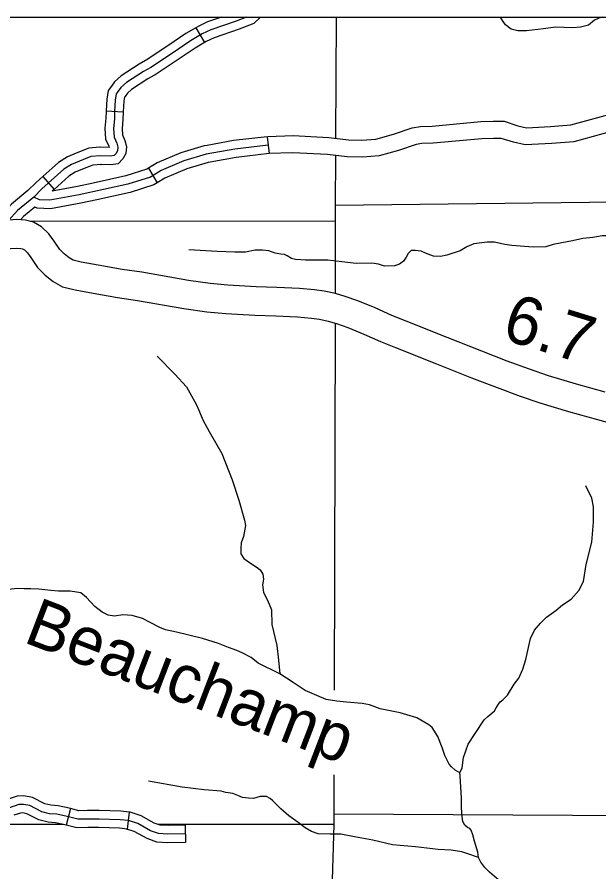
# Model space of a CAD drawing. Extents: x 22866 to 28196, y 1324810 to 1328105.
# Drawn here: x 25280.6 to 25403.3, y 1326401.4 to 1326581.6 of the extents above; entities that cross this region are included whole.
import ezdxf

# ---------------------------------------------------------------- set-up
doc = ezdxf.new("R2010")
doc.units = 0
for name, color, linetype in [('Level 10', 7, 'Continuous'), ('Level 31', 7, 'Continuous'), ('Level 32', 7, 'Continuous'), ('Level 35', 7, 'Continuous'), ('Level 4', 7, 'Continuous'), ('Level 45', 7, 'Continuous'), ('Level 46', 7, 'Continuous'), ('Level 48', 7, 'Continuous'), ('Level 5', 7, 'Continuous'), ('R_No Plot', 7, 'Continuous')]:
    doc.layers.add(name, color=color, linetype=linetype)

msp = doc.modelspace()

# ---------------------------------------------------------------- linework, layer by layer
at = {"layer": 'Level 10'}
for points in [[(25306.99, 1326527.83), (25302.79, 1326528.42), (25297.73, 1326529.32), (25294.15, 1326529.97), (25292.49, 1326530.36), (25291.63, 1326530.87), (25290.58, 1326531.68), (25289.65, 1326532.64), (25288.48, 1326534.39), (25287.37, 1326535.93), (25285.81, 1326537.38), (25284.08, 1326538.4), (25282.44, 1326538.8), (25280.58, 1326538.96), (25278.14, 1326538.75), (25276.47, 1326538.23), (25274.59, 1326537.5), (25272.48, 1326536.58), (25270.72, 1326535.55), (25268.77, 1326534.16), (25266.81, 1326532.28), (25263.07, 1326528.46)], [(25267.33, 1326524.24), (25271.03, 1326528.02), (25272.61, 1326529.53), (25273.97, 1326530.5), (25275.2, 1326531.21), (25276.88, 1326531.95), (25278.45, 1326532.56), (25279.31, 1326532.82), (25280.58, 1326532.93), (25281.47, 1326532.86), (25281.8, 1326532.78), (25282.2, 1326532.54), (25282.84, 1326531.94), (25283.55, 1326530.96), (25284.97, 1326528.84), (25286.57, 1326527.2), (25288.27, 1326525.88), (25290.24, 1326524.73), (25292.92, 1326524.1), (25296.67, 1326523.41), (25301.85, 1326522.49), (25306.06, 1326521.9)], [(25404.64, 1326502.53), (25398.59, 1326504.25), (25392.71, 1326506.01), (25388.71, 1326507.36), (25384.01, 1326509.11), (25378.64, 1326511.18), (25371.32, 1326514.08), (25362.69, 1326517.5), (25359.67, 1326518.74), (25356.14, 1326520.31), (25352.49, 1326521.83), (25349.84, 1326522.7), (25347.81, 1326523.34), (25345.42, 1326523.87), (25343.38, 1326524.13), (25340.18, 1326524.41), (25335.45, 1326524.62), (25331.08, 1326524.77), (25325.08, 1326525.12), (25321.36, 1326525.43), (25316.81, 1326526.12), (25306.99, 1326527.83)], [(25306.06, 1326521.9), (25315.84, 1326520.19), (25320.66, 1326519.46), (25324.66, 1326519.14), (25330.79, 1326518.78), (25335.22, 1326518.62), (25339.79, 1326518.43), (25342.73, 1326518.16), (25344.39, 1326517.95), (25346.26, 1326517.53), (25348.01, 1326516.99), (25350.4, 1326516.2), (25353.76, 1326514.8), (25357.31, 1326513.22), (25360.44, 1326511.94), (25369.12, 1326508.5), (25376.45, 1326505.6), (25381.88, 1326503.5), (25386.71, 1326501.7), (25390.9, 1326500.29), (25396.91, 1326498.49), (25403.04, 1326496.75), (25409.63, 1326494.97)]]:
    msp.add_lwpolyline(points, dxfattribs=at)
at = {"layer": 'Level 31'}
msp.add_lwpolyline([(25316.15, 1326409.43), (25312.46, 1326409.36), (25310.46, 1326409.47), (25308.81, 1326410.05), (25306.08, 1326411.59), (25304.14, 1326412.21), (25302.39, 1326412.39), (25297.94, 1326412.54), (25295.53, 1326412.54), (25293.45, 1326412.5), (25291.19, 1326413.08), (25289.03, 1326413.56), (25287.48, 1326413.67), (25285.87, 1326414.07), (25283.32, 1326415.38), (25281.97, 1326415.64), (25281.02, 1326415.6), (25278.86, 1326414.87)], dxfattribs=at)
at = {"layer": 'Level 32'}
for p, q in [((25291.93, 1326414.75), (25291.03, 1326411.26)), ((25304.27, 1326414), (25303.89, 1326410.42)), ((25316.11, 1326411.23), (25316.19, 1326407.63))]:
    msp.add_line(p, q, dxfattribs=at)
for points in [[(25291.93, 1326414.75), (25291.61, 1326414.83), (25289.29, 1326415.34), (25287.76, 1326415.45), (25286.51, 1326415.77), (25283.91, 1326417.1), (25282.1, 1326417.45), (25280.69, 1326417.39), (25278.78, 1326416.75)], [(25304.27, 1326414), (25302.51, 1326414.19), (25297.97, 1326414.34), (25295.51, 1326414.34), (25293.66, 1326414.3), (25291.93, 1326414.75)], [(25291.03, 1326411.26), (25290.77, 1326411.33), (25288.77, 1326411.77), (25287.19, 1326411.88), (25285.23, 1326412.37), (25282.73, 1326413.66), (25281.83, 1326413.83), (25281.35, 1326413.81), (25279.94, 1326413.34)], [(25316.11, 1326411.23), (25312.5, 1326411.16), (25310.81, 1326411.25), (25309.56, 1326411.7), (25306.8, 1326413.24), (25304.51, 1326413.98), (25304.27, 1326414)], [(25303.89, 1326410.42), (25302.27, 1326410.59), (25297.91, 1326410.74), (25295.55, 1326410.74), (25293.24, 1326410.69), (25291.03, 1326411.26)], [(25316.19, 1326407.63), (25312.43, 1326407.56), (25310.1, 1326407.68), (25308.07, 1326408.41), (25305.35, 1326409.93), (25303.77, 1326410.44), (25303.89, 1326410.42)]]:
    msp.add_lwpolyline(points, dxfattribs=at)
at = {"layer": 'Level 35'}
for points in [[(25402.45, 1326580.94), (25401.14, 1326579.94), (25399.5, 1326579.47), (25397.86, 1326579.33), (25396.04, 1326579.4), (25394.19, 1326579.51), (25391.66, 1326579.15), (25388.06, 1326578.76), (25386.24, 1326578.76), (25384.85, 1326579.08), (25383.64, 1326580.01), (25383.03, 1326580.9), (25382.63, 1326581.62)], [(25404.12, 1326581.62), (25403.7, 1326581.54), (25402.45, 1326580.94)], [(25410.9, 1326535.57), (25407.81, 1326535.57), (25405.06, 1326535.54), (25404.03, 1326535.54), (25402.07, 1326535.18), (25399.96, 1326534.96), (25397.79, 1326534.43), (25395.54, 1326534), (25393.73, 1326533.68), (25392.19, 1326533.18), (25389.52, 1326533.11), (25387.66, 1326533.25), (25384.99, 1326533.47), (25383.53, 1326533.71), (25381.32, 1326534.14), (25379.75, 1326534.14), (25376.98, 1326533.82), (25375.48, 1326533.22)], [(25330.89, 1326532.47), (25328.8, 1326532.04), (25326.55, 1326532.04), (25322.84, 1326532.18), (25316.85, 1326532.57)], [(25349.14, 1326530.04), (25346.15, 1326530.36), (25344.94, 1326530.36), (25341.45, 1326530.4), (25340.52, 1326530.43), (25339.38, 1326530.5), (25338.49, 1326530.75), (25337.6, 1326531.29), (25337.06, 1326531.54), (25336.28, 1326531.61), (25335.06, 1326531.82), (25333.71, 1326532.36), (25332.39, 1326532.47), (25331.75, 1326532.5), (25330.89, 1326532.47)], [(25375.48, 1326533.22), (25374.06, 1326532.32), (25371.28, 1326531.43), (25369.96, 1326531.15), (25368.49, 1326531.22), (25366.78, 1326531.86), (25365.89, 1326532.29), (25364.57, 1326532.43), (25363.79, 1326532.39), (25363.15, 1326531.75), (25362.68, 1326531.04), (25362.11, 1326530.15), (25361.29, 1326529.5), (25360.26, 1326529.15), (25358.16, 1326529.11), (25356.84, 1326529.5), (25355.45, 1326529.75), (25352.13, 1326529.68), (25349.14, 1326530.04)], [(25310.19, 1326510.11), (25313.89, 1326506.32), (25316.39, 1326503.68), (25318.46, 1326499.9), (25319.88, 1326496.55), (25321.17, 1326494.26), (25323.81, 1326489.62), (25326.02, 1326484.06), (25327.44, 1326479.77), (25328.58, 1326475.56), (25328.8, 1326474.47), (25328.37, 1326472.12), (25327.87, 1326470.76), (25327.8, 1326469.69), (25327.8, 1326468.48), (25328.44, 1326467.48), (25329.87, 1326466.48), (25331.29, 1326465.55), (25331.93, 1326465.12), (25332.5, 1326464.19), (25332.58, 1326463.12), (25332.43, 1326461.91), (25332.58, 1326460.34), (25333.43, 1326458.7), (25334.29, 1326456.63), (25334.36, 1326453.56), (25335.43, 1326449.13), (25335.78, 1326446.06), (25336.07, 1326443.14)], [(25387.94, 1326446.17), (25388.94, 1326450.59), (25389.74, 1326452.4), (25391.02, 1326453.81), (25392.29, 1326455.09), (25394.3, 1326456.49), (25395.64, 1326457.7), (25397.52, 1326458.91), (25399.12, 1326460.72), (25400.13, 1326462.66), (25400.66, 1326466.22), (25401.87, 1326470.91), (25402.2, 1326475.11), (25402.2, 1326478.39), (25401.87, 1326480.2), (25400.6, 1326482.82)], [(25336.07, 1326443.14), (25331.51, 1326445.44), (25330.01, 1326446.59), (25328.15, 1326447.58), (25327.01, 1326448.08), (25325.23, 1326448.73), (25323.09, 1326449.58), (25319.74, 1326450.58), (25314.25, 1326451.94), (25311.97, 1326452.44), (25310.76, 1326452.94), (25308.69, 1326454.01), (25307.12, 1326454.86), (25304.91, 1326455.44), (25302.98, 1326455.58), (25301.2, 1326455.29), (25299.85, 1326455.51), (25298.56, 1326456.15), (25297.07, 1326457.36), (25295.28, 1326459.29), (25294.07, 1326460.22), (25291.86, 1326460.57), (25289.37, 1326460.57), (25287.73, 1326460.72), (25285.23, 1326461), (25283.52, 1326461.07), (25282.16, 1326461.07), (25280.67, 1326461.15), (25278.88, 1326460.93)], [(25374.01, 1326422.29), (25374.48, 1326423.31), (25374.81, 1326425.49), (25375.79, 1326428.3), (25377.26, 1326430.58), (25379.17, 1326433.43), (25379.91, 1326434.17), (25380.78, 1326434.84), (25381.35, 1326435.34), (25381.65, 1326435.98), (25382.18, 1326436.78), (25382.52, 1326437.25), (25383.12, 1326437.65), (25383.66, 1326438.22), (25384.06, 1326438.66), (25385.5, 1326441.01), (25386.47, 1326442.25), (25387.34, 1326444.12), (25387.94, 1326446.17)], [(25357.2, 1326435.81), (25355, 1326436.65), (25353.42, 1326436.92), (25350.14, 1326437.18), (25348.1, 1326437.42), (25345.85, 1326437.75), (25343.38, 1326438.79), (25341.37, 1326439.67), (25338.85, 1326441.31), (25336.07, 1326443.14)], [(25374.01, 1326422.29), (25373.07, 1326422.87), (25372.27, 1326423.54), (25371.77, 1326424.14), (25370.86, 1326425.92), (25370.26, 1326427.66), (25369.36, 1326429.98), (25368.18, 1326431.82), (25367.45, 1326432.42), (25364.97, 1326433.87), (25361.42, 1326434.94), (25357.2, 1326435.81)], [(25376.41, 1326410.21), (25376.12, 1326410.53), (25375.62, 1326410.73), (25375.08, 1326411.23), (25374.68, 1326412.04), (25374.48, 1326413.11), (25374.35, 1326414.89), (25374.35, 1326416.96), (25374.11, 1326421.69), (25374.01, 1326422.29)], [(25320.09, 1326418.71), (25315.46, 1326419.28), (25308.36, 1326420.56)], [(25348.92, 1326409.35), (25346.68, 1326409.35), (25344.17, 1326409.45), (25342.76, 1326409.92), (25341.42, 1326410.66), (25339.95, 1326411.8), (25337.97, 1326413.24), (25336.3, 1326414.72), (25335.46, 1326415.52), (25334.59, 1326416.39), (25333.99, 1326416.86), (25333.25, 1326417.3), (25331.91, 1326417.33), (25330.54, 1326416.9), (25329.47, 1326416.93), (25328.16, 1326417.06), (25327.22, 1326417.53), (25326.15, 1326417.9), (25324.68, 1326418.17), (25323.71, 1326418.44), (25320.09, 1326418.71)], [(25372.2, 1326405.97), (25369.45, 1326406.14), (25364.69, 1326406.71), (25359.84, 1326407.14), (25355.68, 1326408.08), (25351.83, 1326408.78), (25348.92, 1326409.35)], [(25398.17, 1326391.05), (25396.6, 1326391.77), (25395.36, 1326392.24), (25393.99, 1326392.71), (25392.75, 1326393.38), (25391.58, 1326394.11), (25390.67, 1326394.78), (25389.2, 1326395.52), (25387.62, 1326395.92), (25386.55, 1326396.46), (25385.62, 1326397.17), (25384.81, 1326397.97), (25383.64, 1326398.91), (25382.07, 1326399.81), (25381.26, 1326400.48), (25380.26, 1326401.32), (25379.32, 1326402.33), (25378.48, 1326403.43), (25377.98, 1326404.47), (25377.81, 1326405.58), (25377.11, 1326407.86), (25376.77, 1326409.23), (25376.41, 1326410.21)], [(25377.98, 1326404.47), (25375.51, 1326405.3), (25374.41, 1326405.63), (25372.2, 1326405.97)]]:
    msp.add_lwpolyline(points, dxfattribs=at)
at = {"layer": 'Level 4'}
for points in [[(25347.96, 1326581.62), (25347.83, 1326556.05)], [(25347.81, 1326552.43), (25347.76, 1326541.88), (25347.75, 1326538.61), (25347.71, 1326523.37)], [(25347.7, 1326517.09), (25347.52, 1326439.69)], [(25347.48, 1326421.9), (25347.46, 1326413.55), (25347.42, 1326411.43), (25343.71, 1326287.42)]]:
    msp.add_lwpolyline(points, dxfattribs=at)
at = {"layer": 'Level 45'}
for p, q in [((25318.31, 1326579.35), (25320.15, 1326576.25)), ((25299.43, 1326561.89), (25303.02, 1326561.68)), ((25333.36, 1326556.41), (25333.78, 1326552.84)), ((25308.35, 1326549.76), (25310.22, 1326546.68)), ((25286.07, 1326547.99), (25288.48, 1326545.3))]:
    msp.add_line(p, q, dxfattribs=at)
for points in [[(25329, 1326581.62), (25326.85, 1326580.79), (25321.51, 1326578.95), (25319.66, 1326578.06), (25317.23, 1326576.62), (25313.42, 1326574.04), (25308.83, 1326570.99), (25307.29, 1326570.13), (25303.69, 1326567.8), (25302.56, 1326566.77), (25301.98, 1326565.98), (25301.57, 1326565.43), (25301.36, 1326564.12), (25301.22, 1326561.72), (25301.16, 1326560.17), (25300.98, 1326558.14), (25301.09, 1326556.32), (25301.7, 1326555.02), (25301.91, 1326554.23), (25301.81, 1326553.44), (25301.46, 1326552.79), (25301.09, 1326552.41), (25300.33, 1326552.31), (25298.24, 1326552.38), (25296.22, 1326552.21), (25293.78, 1326551.24), (25292.1, 1326550.56), (25290.49, 1326549.53)], [(25323.74, 1326581.62), (25320.83, 1326580.62), (25318.81, 1326579.65), (25318.31, 1326579.35)], [(25331.95, 1326581.62), (25330.59, 1326580.3), (25327.47, 1326579.1), (25322.2, 1326577.28), (25320.51, 1326576.47), (25320.15, 1326576.25)], [(25318.31, 1326579.35), (25316.26, 1326578.14), (25312.42, 1326575.54), (25307.89, 1326572.53), (25307.74, 1326572.45)], [(25320.15, 1326576.25), (25318.19, 1326575.1), (25314.42, 1326572.55), (25309.77, 1326569.45), (25309.5, 1326569.3)], [(25307.74, 1326572.45), (25306.36, 1326571.67), (25302.59, 1326569.23), (25301.22, 1326567.98), (25300.53, 1326567.05), (25299.86, 1326566.15), (25299.57, 1326564.32), (25299.43, 1326561.89)], [(25309.5, 1326569.3), (25308.22, 1326568.59), (25304.8, 1326566.37), (25303.9, 1326565.56), (25303.42, 1326564.9), (25303.28, 1326564.71), (25303.15, 1326563.93), (25303.02, 1326561.68)], [(25299.43, 1326561.89), (25299.43, 1326561.81), (25299.36, 1326560.28), (25299.18, 1326558.17), (25299.31, 1326555.87), (25300, 1326554.4), (25300.08, 1326554.12), (25298.19, 1326554.18), (25298.07, 1326554.17)], [(25303.02, 1326561.68), (25303.02, 1326561.63), (25302.95, 1326560.05), (25302.79, 1326558.12), (25302.86, 1326556.78), (25303.4, 1326555.64), (25303.74, 1326554.35), (25303.55, 1326552.89), (25302.93, 1326551.71), (25301.93, 1326550.71), (25300.43, 1326550.5), (25298.29, 1326550.57), (25298.37, 1326550.58)], [(25333.36, 1326556.41), (25326.31, 1326555.58), (25320.72, 1326554.56)], [(25333.57, 1326554.62), (25326.58, 1326553.8), (25320.54, 1326552.7), (25315.81, 1326551.33), (25311.01, 1326549.27), (25308.75, 1326547.9), (25304.01, 1326546.39), (25293.73, 1326544.12), (25287.55, 1326543.02), (25285.36, 1326543.09), (25284.15, 1326543.69)], [(25298.07, 1326554.17), (25295.8, 1326553.98), (25293.11, 1326552.91), (25291.27, 1326552.16), (25289.4, 1326550.97), (25286.07, 1326547.99)], [(25320.72, 1326554.56), (25320.13, 1326554.46), (25315.2, 1326553.03), (25310.18, 1326550.88), (25308.35, 1326549.76)], [(25333.78, 1326552.84), (25326.85, 1326552.02), (25321.36, 1326551.02)], [(25298.37, 1326550.58), (25296.63, 1326550.43), (25294.45, 1326549.57), (25292.93, 1326548.95), (25291.58, 1326548.09), (25288.48, 1326545.3)], [(25308.35, 1326549.76), (25308, 1326549.55), (25303.55, 1326548.13), (25296.71, 1326546.62)], [(25321.36, 1326551.02), (25320.96, 1326550.95), (25316.42, 1326549.63), (25311.84, 1326547.67), (25310.22, 1326546.68)], [(25286.07, 1326547.99), (25284.66, 1326546.72), (25282.94, 1326545.03), (25279.47, 1326542.18), (25277.31, 1326539.75), (25276.62, 1326538.28)], [(25290.49, 1326549.53), (25285.9, 1326545.41), (25284.15, 1326543.69), (25280.72, 1326540.88), (25278.83, 1326538.75), (25278.25, 1326537.52), (25277.46, 1326535.39)], [(25296.71, 1326546.62), (25293.38, 1326545.89), (25288.08, 1326544.95)], [(25310.22, 1326546.68), (25309.5, 1326546.25), (25304.48, 1326544.65), (25297.49, 1326543.11)], [(25288.48, 1326545.3), (25288.08, 1326544.95)], [(25297.49, 1326543.11), (25294.08, 1326542.36), (25287.69, 1326541.22), (25284.91, 1326541.31), (25284.39, 1326541.56)], [(25284.39, 1326541.56), (25281.97, 1326539.58), (25281.36, 1326538.89)]]:
    msp.add_lwpolyline(points, dxfattribs=at)
at = {"layer": 'Level 46'}
for points in [[(25333.5, 1326556.42), (25338.84, 1326556.63), (25346.38, 1326556.21), (25350.54, 1326555.74), (25353.37, 1326555.67), (25356.33, 1326555.92), (25360.03, 1326556.96), (25363.98, 1326558.31), (25365.69, 1326558.55), (25368.2, 1326558.62), (25378.42, 1326559.58), (25381.04, 1326559.65), (25383.34, 1326559.65), (25386.28, 1326558.7), (25388.08, 1326558.29), (25393.16, 1326558.55), (25397.43, 1326558.88), (25407.27, 1326561.58)], [(25408.22, 1326558.11), (25398.05, 1326555.31), (25393.39, 1326554.96), (25387.77, 1326554.67), (25385.32, 1326555.22), (25382.77, 1326556.05), (25381.09, 1326556.05), (25378.64, 1326555.99), (25368.42, 1326555.02), (25366, 1326554.96), (25364.82, 1326554.79), (25361.1, 1326553.52), (25356.98, 1326552.37), (25353.49, 1326552.07), (25350.29, 1326552.14), (25346.08, 1326552.62), (25338.81, 1326553.03), (25333.65, 1326552.83)]]:
    msp.add_lwpolyline(points, dxfattribs=at)
at = {"layer": 'Level 5'}
for points in [[(25472.87, 1326543.36), (25347.76, 1326541.88)], [(25347.75, 1326538.61), (25283.5, 1326538.54)], [(25473.2, 1326412.84), (25347.46, 1326413.55)], [(25290.41, 1326411.41), (25221.42, 1326411.39)], [(25347.42, 1326411.43), (25310.35, 1326411.42)]]:
    msp.add_lwpolyline(points, dxfattribs=at)
at = {"layer": 'R_No Plot'}
msp.add_lwpolyline([(24815.02, 1326581.62), (26086.71, 1326581.62), (26086.71, 1325755.52), (24815.02, 1325755.52)], close=True, dxfattribs=at)
msp.add_lwpolyline([(24815.02, 1326581.62), (26086.71, 1326581.62), (26086.71, 1325755.52), (24815.02, 1325755.52)], close=True, dxfattribs=at)

# ---------------------------------------------------------------- texts
at = {"layer": 'Level 35'}
msp.add_text('Beauchamp', height=10.139, rotation=339.046, dxfattribs=at).set_placement((25281.71, 1326449.93))
at = {"layer": 'Level 48'}
msp.add_text('6.7', height=10.139, rotation=342.7833, dxfattribs=at).set_placement((25382.54, 1326513.87))

doc.saveas('drawing.dxf')
